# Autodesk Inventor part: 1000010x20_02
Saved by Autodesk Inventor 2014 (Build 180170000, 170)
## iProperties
Company: TraceParts S.A.
Created: 2015-09
Part Number: 1000010x20_02
Checked By: TraceParts S.A.
Catalog Web Link: www.traceparts.com
Document SubType Name: Modeling
Designer: TraceParts
Material: Générique
Density: 1 g/cm^3
Appearance: 128,128,128
Author: TraceParts
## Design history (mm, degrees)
feature "1000010x20"
node "Solide1"
node "Corps solides"
node "Corps surfaciques"
